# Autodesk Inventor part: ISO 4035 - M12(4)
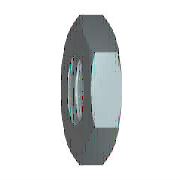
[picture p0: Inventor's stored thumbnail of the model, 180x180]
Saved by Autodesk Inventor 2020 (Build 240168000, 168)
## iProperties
Created: 2019-01
Part Number: ISO 4035 - M12(4)
Material: Nerezová ocel 440C
Description: Šestihranné matice nízké se zkosením – Výrobní třída A a B
Document SubType Name: Modeling
Standard: ISO 4035
Designer: doma
Standard Revision: Fourth edition 2012-12-15
Standards Organization: ISO
Language: cs-CZ
Size Designation: M12
Categories: <MemberInstance><Categories><Category DisplayName="Spojovací materiál" InternalName="e4da775c-781d-43d5-af7c-5136215cf5a6" Mnemonic="FSTN"><Category DisplayName
Density: 7.75 g/cm^3
Appearance: Pololeštěná
Author: doma
IsCustomPart: 0
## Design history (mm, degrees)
sketch "Náčrt1"
  geometry: L1 (-10.392, 0)-(-5.196, 9); L2 (-5.196, 9)-(5.196, 9); L3 (5.196, 9)-(10.392, 0); L4 (10.392, 0)-(5.196, -9); L5 (5.196, -9)-(-5.196, -9); L6 (-5.196, -9)-(-10.392, 0); 2 further points
  constraints: 12 end point, 1 coincident, 1 horizontal, 11 other
  dimensions: "d0" = 20.78461 distance of L3.end L1.start (= 1.1547 x SW)
extrude "Těleso" new body sketch "Náčrt1" distance "d1" = 6 (= KOH); taper "d2" = 0 deg
sketch "Náčrt2"
  geometry: L1 (0, 5.196)-(0, 10.392) reference; L2 (0, 10.392)-(6, 10.392) reference; L3 (6, 5.196)-(6, 10.392) reference; L4 (-1.2, 0)-(7.2, 0) reference; L5 (1.208, 10.392)-(0, 8.3); L6 (4.792, 10.392)-(6, 8.3)
  constraints: 4 end point, 4 point on line
  dimensions: "d3" = 30 deg angle of L1 L5 (= ANG1); "d4" = 30 deg angle of L3 L6 (= ANG2); "d5" = 16.6 diameter of L5.end L4 (= SW0); "d6" = 16.6 diameter of L6.end L4 (= SW01)
revolve "Zkosení1" sketch "Náčrt2" stored, may be unused: angle "d7" = 90 deg
sketch "Náčrt3"
  geometry: 4 further points
  constraints: 1 coincident, 1 other
hole "Závit" sketch "Náčrt3" at (0, 0) diameter "d25" = 10.106; stored, may be unused: countersink angle "d29" = 82 deg, drill point angle "d31" = 118 deg; dims "d26" = 6, "d27" = 4, "d28" = 2, "d30" = 8
workaxis "Work Axis1"
workplane "Work Plane1"
body "Solid1"
chamfer "Zkosení2" distance "d8" = 0.94722 (= -0.5 x GD1 + 0.5 x NND); stored, may be unused: angle "d9" = 30 deg, second distance "d40" = 0.94722 (= -0.5 x GD1 + 0.5 x NND)
chamfer "Zkosení3" distance "d10" = 0.94722 (= -0.5 x GD1 + 0.5 x NND); stored, may be unused: angle "d11" = 30 deg, second distance "d41" = 0.94722 (= -0.5 x GD1 + 0.5 x NND)
other parameters: "ANG1" = 30 deg [user parameter; used in 1 equation term], "ANG2" = 30 deg [user parameter; used in 1 equation term], "NND" = 12 [user parameter; used in 4 equation terms], "KOH" = 6 [user parameter; used in 1 equation term], "SW" = 18 [user parameter; used in 2 equation terms], "SW0" = 16.6 [user parameter; used in 2 equation terms], "SW01" = 16.6 (= SW0) [user parameter; used in 1 equation term], "GD1" = 10.10557 (computed from THREADDIA, PTC, TOA) [user parameter; used in 4 equation terms], "d13" = 0, "d14" = 0, "d39" = 0, "d42" = 0, "GUL" = 0.94722 (= 0.541266 x PTC) [user parameter], "TPU" = 5.71429 (computed from PTC) [user parameter], "THREADDIA" = 12 [user parameter; used in 1 equation term], "TOA" = 30 deg [user parameter; used in 1 equation term], "PTC" = 1.75 [user parameter; used in 4 equation terms], "E0" = 20.79 (= 1.155 x SW) [user parameter], "GAL" = 0.94722 (= 0.541266 x PTC) [user parameter]
